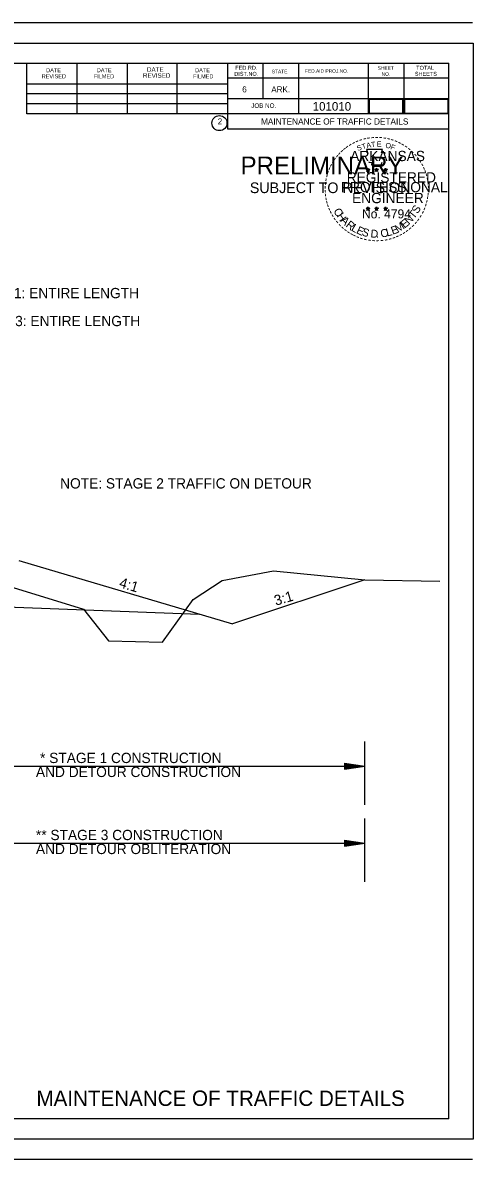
# Model space of a CAD drawing. Extents: x 6125 to 14104, y 8730 to 11067.
# Drawn here: x 9345 to 9784, y 9961 to 11067 of the extents above; entities that cross this region are included whole.
import ezdxf

# ---------------------------------------------------------------- set-up
doc = ezdxf.new("R2010")
doc.units = 0
for name, color, linetype in [('C-PSVP', 7, 'Continuous'), ('GREEN_TXT', 7, 'Continuous'), ('R_Border Notes', 7, 'Continuous'), ('R_No Plot', 7, 'Continuous'), ('R_Proposed Road', 7, 'Continuous'), ('SEAL-INFO', 7, 'Continuous'), ('SIGNATURE', 7, 'Continuous'), ('Stage 1 Construction', 7, 'Continuous'), ('Stage 3', 7, 'Continuous')]:
    doc.layers.add(name, color=color, linetype=linetype)

msp = doc.modelspace()

# ---------------------------------------------------------------- linework, layer by layer
for p, q in [((9340.6, 10543.3), (9548.9, 10481.6)), ((9678, 10524.6), (9548.9, 10481.6)), ((9198.9, 10503.1), (9516.5, 10491.2))]:
    msp.add_line(p, q)
at = {"layer": 'C-PSVP'}
for p, q in [((9679.2, 10924), (9680.9, 10923.5)), ((9679.2, 10924), (9680.4, 10923.8)), ((9679.2, 10924), (9680.3, 10923.4)), ((9679.8, 10922), (9680.9, 10923.5)), ((9679.8, 10922), (9680.4, 10923.2)), ((9679.8, 10922), (9680.9, 10923.1)), ((9680.9, 10925.3), (9680.7, 10924.1)), ((9680.9, 10923.5), (9680.9, 10925.3)), ((9680.9, 10925.3), (9681.1, 10924.1)), ((9682.6, 10924), (9680.9, 10923.5)), ((9682, 10922), (9680.9, 10923.5)), ((9682, 10922), (9680.9, 10923.1)), ((9682.6, 10924), (9681.2, 10923.8)), ((9682, 10922), (9681.3, 10923.5)), ((9682.6, 10924), (9681.6, 10923.5)), ((9687.5, 10924), (9689.2, 10923.5)), ((9687.5, 10924), (9688.8, 10923.8)), ((9687.5, 10924), (9688.7, 10923.4)), ((9688.2, 10922), (9689.2, 10923.5)), ((9688.2, 10922), (9688.8, 10923.2)), ((9688.2, 10922), (9689.2, 10923.1)), ((9689.2, 10925.3), (9689, 10924.1)), ((9689.2, 10923.5), (9689.2, 10925.3)), ((9689.2, 10925.3), (9689.5, 10924.1)), ((9691, 10924), (9689.2, 10923.5)), ((9690.3, 10922), (9689.2, 10923.5)), ((9690.3, 10922), (9689.2, 10923.1)), ((9691, 10924), (9689.6, 10923.8)), ((9690.3, 10922), (9689.6, 10923.5)), ((9691, 10924), (9690, 10923.5)), ((9696.3, 10924), (9698.1, 10923.4)), ((9696.3, 10924), (9697.6, 10923.8)), ((9696.3, 10924), (9697.5, 10923.4)), ((9697, 10921.9), (9698.1, 10923.4)), ((9697, 10921.9), (9697.6, 10923.2)), ((9697, 10921.9), (9698.1, 10923)), ((9698.1, 10925.3), (9697.9, 10924)), ((9698.1, 10923.4), (9698.1, 10925.3)), ((9698.1, 10925.3), (9698.3, 10924)), ((9699.8, 10924), (9698.1, 10923.4)), ((9699.1, 10921.9), (9698.1, 10923.4)), ((9699.1, 10921.9), (9698.1, 10923)), ((9699.8, 10924), (9698.4, 10923.7)), ((9699.1, 10921.9), (9698.4, 10923.4)), ((9699.8, 10924), (9698.8, 10923.5)), ((9679.1, 10886.2), (9680.9, 10885.6)), ((9679.1, 10886.2), (9680.4, 10886)), ((9679.1, 10886.2), (9680.3, 10885.6)), ((9679.8, 10884.1), (9680.9, 10885.6)), ((9679.8, 10884.1), (9680.4, 10885.4)), ((9679.8, 10884.1), (9680.9, 10885.2)), ((9680.9, 10887.4), (9680.7, 10886.2)), ((9680.9, 10885.6), (9680.9, 10887.4)), ((9680.9, 10887.4), (9681.1, 10886.2)), ((9682.6, 10886.2), (9680.9, 10885.6)), ((9681.9, 10884.1), (9680.9, 10885.6)), ((9681.9, 10884.1), (9680.9, 10885.2)), ((9682.6, 10886.2), (9681.2, 10885.9)), ((9681.9, 10884.1), (9681.3, 10885.6)), ((9682.6, 10886.2), (9681.6, 10885.7)), ((9687.5, 10886.2), (9689.2, 10885.6)), ((9687.5, 10886.2), (9688.7, 10886)), ((9687.5, 10886.2), (9688.7, 10885.6)), ((9688.1, 10884.1), (9689.2, 10885.6)), ((9688.1, 10884.1), (9688.8, 10885.4)), ((9688.1, 10884.1), (9689.2, 10885.2)), ((9689.2, 10887.4), (9689, 10886.2)), ((9689.2, 10885.6), (9689.2, 10887.4)), ((9689.2, 10887.4), (9689.5, 10886.2)), ((9691, 10886.2), (9689.2, 10885.6)), ((9690.3, 10884.1), (9689.2, 10885.6)), ((9690.3, 10884.1), (9689.2, 10885.2)), ((9691, 10886.2), (9689.5, 10885.9)), ((9690.3, 10884.1), (9689.6, 10885.6)), ((9691, 10886.2), (9689.9, 10885.7)), ((9696.3, 10886.1), (9698.1, 10885.6)), ((9696.3, 10886.1), (9697.6, 10885.9)), ((9696.3, 10886.1), (9697.5, 10885.5)), ((9697, 10884.1), (9698.1, 10885.6)), ((9697, 10884.1), (9697.6, 10885.3)), ((9697, 10884.1), (9698, 10885.2)), ((9698.1, 10887.4), (9697.9, 10886.1)), ((9699.1, 10884.1), (9698, 10885.2)), ((9698.1, 10885.6), (9698.1, 10887.4)), ((9698.1, 10887.4), (9698.3, 10886.1)), ((9699.8, 10886.1), (9698.1, 10885.6)), ((9699.1, 10884.1), (9698.1, 10885.6)), ((9699.8, 10886.1), (9698.4, 10885.9)), ((9699.1, 10884.1), (9698.4, 10885.5)), ((9699.8, 10886.1), (9698.8, 10885.6))]:
    msp.add_line(p, q, dxfattribs=at)
for points in [[(9679.4, 10943.4), (9680.7, 10939.3)], [(9696.9, 10938.8), (9697.6, 10940.2), (9694.2, 10940.1), (9694.9, 10943.4), (9679.4, 10943.4)], [(9681.8, 10931.3), (9681.8, 10930.9), (9684.6, 10930.8), (9684.4, 10928.4), (9693.7, 10928.4), (9694.7, 10931.1)], [(9680.9, 10925.3), (9682, 10922), (9679.2, 10924), (9682.6, 10924), (9679.8, 10922), (9680.9, 10925.3)], [(9689.2, 10925.3), (9690.3, 10922), (9687.5, 10924), (9691, 10924), (9688.2, 10922), (9689.2, 10925.3)], [(9698.1, 10925.3), (9699.1, 10921.9), (9696.3, 10924), (9699.8, 10924), (9697, 10921.9), (9698.1, 10925.3)], [(9680.9, 10887.4), (9681.9, 10884.1), (9679.1, 10886.2), (9682.6, 10886.2), (9679.8, 10884.1), (9680.9, 10887.4)], [(9689.2, 10887.4), (9690.3, 10884.1), (9687.5, 10886.2), (9691, 10886.2), (9688.1, 10884.1), (9689.2, 10887.4)], [(9698.1, 10887.4), (9699.1, 10884.1), (9696.3, 10886.1), (9699.8, 10886.1), (9697, 10884.1), (9698.1, 10887.4)]]:
    msp.add_lwpolyline(points, dxfattribs=at)
for centre, radius in [((9680.9, 10923.5), 0.861), ((9680.9, 10923.5), 0.723), ((9680.9, 10923.5), 0.579), ((9680.9, 10923.5), 0.495), ((9680.9, 10923.5), 0.374), ((9680.9, 10923.5), 0.248), ((9680.9, 10923.5), 0.148), ((9689.2, 10923.5), 0.861), ((9689.2, 10923.5), 0.723), ((9689.2, 10923.5), 0.579), ((9689.2, 10923.5), 0.495), ((9689.2, 10923.5), 0.374), ((9689.2, 10923.5), 0.248), ((9689.2, 10923.5), 0.148), ((9698.1, 10923.4), 0.861), ((9698.1, 10923.4), 0.723), ((9698.1, 10923.4), 0.579), ((9698.1, 10923.4), 0.495), ((9698.1, 10923.4), 0.374), ((9698.1, 10923.4), 0.248), ((9698.1, 10923.4), 0.148), ((9680.9, 10885.6), 0.861), ((9680.9, 10885.6), 0.723), ((9680.9, 10885.6), 0.579), ((9680.9, 10885.6), 0.495), ((9680.9, 10885.6), 0.374), ((9680.9, 10885.6), 0.248), ((9680.9, 10885.6), 0.148), ((9689.2, 10885.6), 0.861), ((9689.2, 10885.6), 0.723), ((9689.2, 10885.6), 0.579), ((9689.2, 10885.6), 0.495), ((9689.2, 10885.6), 0.374), ((9689.2, 10885.6), 0.248), ((9689.2, 10885.6), 0.148), ((9698.1, 10885.6), 0.861), ((9698.1, 10885.6), 0.723), ((9698.1, 10885.6), 0.579), ((9698.1, 10885.6), 0.495), ((9698.1, 10885.6), 0.374), ((9698.1, 10885.6), 0.248), ((9698.1, 10885.6), 0.148)]:
    msp.add_circle(centre, radius, dxfattribs=at)
at = {"layer": 'GREEN_TXT'}
for p, q in [((9782.7, 11066.7), (8022.7, 11066.7)), ((8178.8, 11027.3), (9759.7, 11027.3)), ((9348.4, 10977.9), (9348.4, 11027.3)), ((9397.7, 10977.9), (9397.7, 11026.3)), ((9446.5, 10977.9), (9446.5, 11026.3)), ((9494.9, 10977.9), (9494.9, 11026.3)), ((9544.2, 11027.3), (9544.2, 10963.3)), ((9578.4, 11027.3), (9578.4, 10992.6)), ((9613.1, 11027.3), (9613.1, 10977.9)), ((9681, 11027.3), (9681, 10977.9)), ((9715.7, 11027.3), (9715.7, 10977.9)), ((9759.7, 10000), (9759.7, 11027.3)), ((9348.4, 11007.2), (9544.2, 11007.2)), ((9759.7, 11012.6), (9544.2, 11012.6)), ((9759.7, 11012.7), (9759.7, 11012.7)), ((9348.4, 10997.9), (9544.2, 10997.9)), ((9348.4, 10988.2), (9544.2, 10988.2)), ((9759.7, 10992.6), (9544.2, 10992.6)), ((9759.7, 10977.9), (9348.4, 10977.9)), ((9544.2, 10963.3), (9759.7, 10963.3)), ((9759.7, 10000), (8178.8, 10000)), ((8022.7, 9960.6), (9782.7, 9960.6))]:
    msp.add_line(p, q, dxfattribs=at)
msp.add_circle((9536.2, 10969), 7.33, dxfattribs=at)
at = {"layer": 'R_No Plot'}
msp.add_lwpolyline([(8214.9, 10518), (8254.7, 10519.4), (8315.6, 10519), (8407.7, 10512.2), (8460.4, 10505.1), (8509.6, 10474.3), (8577.8, 10476.5), (8706.5, 10525.2), (8791.8, 10534.6), (9005.6, 10537.5), (9218.9, 10534.6), (9305.3, 10526.2), (9403.9, 10495.9), (9428.2, 10465.3), (9480.8, 10463.7), (9510.7, 10505.5), (9538.9, 10523.9), (9588.8, 10533.2), (9678, 10524.6), (9750.8, 10523.3)], dxfattribs=at)
at = {"layer": 'R_Proposed Road'}
msp.add_lwpolyline([(9682.1, 10978.6), (9714.7, 10978.6), (9714.7, 10991.9), (9682.1, 10991.9)], close=True, dxfattribs=at)
at = {"layer": 'SEAL-INFO'}
msp.add_lwpolyline([(8116.8, 11046.8), (9783.5, 11046.8), (9783.5, 9980.1), (8116.8, 9980.1)], close=True, dxfattribs=at)
at = {"layer": 'Stage 1 Construction'}
for p, q in [((9678, 10305.7), (9678, 10367.2)), ((9218.9, 10343.2), (9678, 10343.2)), ((9658, 10346.2), (9678, 10343.2)), ((9658, 10346.2), (9658, 10340.2)), ((9658, 10345.7), (9674.7, 10343.2)), ((9658, 10345.1), (9671.2, 10343.2)), ((9658, 10344.6), (9667.9, 10343.2)), ((9658, 10344.1), (9664.5, 10343.2)), ((9658, 10343.6), (9661.2, 10343.2)), ((9658, 10340.2), (9678, 10343.2)), ((9658, 10342.2), (9664.5, 10343.2)), ((9658, 10341.2), (9671.2, 10343.2)), ((9658, 10340.7), (9674.7, 10343.2)), ((9658, 10341.7), (9667.9, 10343.2)), ((9658, 10342.7), (9661.2, 10343.2)), ((9678, 10230.7), (9678, 10292.2)), ((9218.9, 10268.2), (9678, 10268.2)), ((9658, 10271.2), (9678, 10268.2)), ((9658, 10271.2), (9658, 10265.2)), ((9658, 10270.7), (9674.7, 10268.2)), ((9658, 10270.2), (9671.2, 10268.2)), ((9658, 10269.7), (9667.9, 10268.2)), ((9658, 10269.2), (9664.5, 10268.2)), ((9658, 10268.7), (9661.2, 10268.2)), ((9658, 10265.2), (9678, 10268.2)), ((9658, 10267.2), (9664.5, 10268.2)), ((9658, 10266.2), (9671.2, 10268.2)), ((9658, 10265.7), (9674.7, 10268.2)), ((9658, 10266.7), (9667.9, 10268.2)), ((9658, 10267.7), (9661.2, 10268.2))]:
    msp.add_line(p, q, dxfattribs=at)
at = {"layer": 'Stage 3'}
msp.add_lwpolyline([(9716.6, 10978.6), (9758.9, 10978.6), (9758.9, 10991.9), (9716.6, 10991.9)], close=True, dxfattribs=at)

# ---------------------------------------------------------------- texts
at = {"layer": 'C-PSVP'}
for s, height, rotation, p in [('-', 8, 28.7918, (9666.8, 10946.1)), ('-', 8, 24.3072, (9669.9, 10947.7)), ('-', 8, 19.1761, (9673.1, 10949.1)), ('-', 8, 13.6302, (9676.8, 10950.3)), ('-', 8, 10.2193, (9680.2, 10951.1)), ('T', 5, 6.0228, (9684.1, 10945.6)), ('-', 8, 5.8968, (9683.9, 10951.6)), ('-', 8, 0.1862, (9687.7, 10952)), ('E', 5, 0.8323, (9689.6, 10946.1)), ('-', 8, 357.743, (9691.4, 10951.9)), ('-', 8, 352.1617, (9695.1, 10951.6)), ('-', 8, 347.2049, (9698.7, 10951.1)), ('-', 8, 342.3362, (9701.8, 10950.3)), ('-', 8, 337.8551, (9705.5, 10949.2)), ('-', 8, 334.1211, (9708.7, 10947.8)), ('-', 8, 48.4231, (9654.1, 10935.9)), ('-', 8, 42.9622, (9656.3, 10938.3)), ('-', 8, 38.9507, (9658.5, 10940.4)), ('-', 8, 36.2317, (9660.9, 10942.3)), ('-', 8, 34.0636, (9663.8, 10944.3)), ('S', 5, 21.594, (9671.1, 10941.8)), ('T', 5, 16.4036, (9675.7, 10943.5)), ('A', 5, 11.2132, (9679.8, 10944.7)), ('O', 5, 350.4515, (9697.6, 10945.1)), ('F', 5, 340.0707, (9702.4, 10943.9)), ('-', 8, 329.6409, (9711.6, 10946.4)), ('-', 8, 325.8627, (9714.8, 10944.6)), ('-', 8, 320.5297, (9717.8, 10942.5)), ('-', 8, 315.5786, (9720.8, 10940)), ('-', 8, 62.8713, (9646.8, 10925)), ('-', 8, 58.0706, (9648.4, 10928)), ('-', 8, 54.2325, (9650, 10930.7)), ('-', 8, 50.6142, (9652.1, 10933.5)), ('-', 8, 309.8797, (9723.7, 10937.3)), ('-', 8, 306.6522, (9726.3, 10934.3)), ('-', 7, 303.6753, (9728.7, 10931.4)), ('-', 8, 299.6684, (9730.3, 10928.4)), ('-', 8, 75.461, (9643.5, 10915.2)), ('-', 8, 72.3945, (9644.4, 10918.8)), ('-', 8, 67.7743, (9645.5, 10921.9)), ('-', 8, 294.6628, (9731.9, 10925.3)), ('-', 8, 290.5728, (9733.2, 10922.5)), ('-', 8, 285.1233, (9734.4, 10919.6)), ('-', 8, 89.0622, (9642.3, 10904.7)), ('-', 8, 85.1863, (9642.4, 10908.2)), ('-', 8, 81.2013, (9642.8, 10911.6)), ('-', 8, 280.5493, (9735.4, 10915.9)), ('-', 8, 276.5962, (9736.2, 10912)), ('-', 8, 274.3301, (9736.5, 10908.4)), ('-', 8, 94.1959, (9642.5, 10901.1)), ('-', 8, 98.9479, (9642.8, 10897.7)), ('-', 8, 101.7149, (9643.5, 10894.1)), ('-', 8, 260.9953, (9736.2, 10898.6)), ('-', 8, 263.5172, (9736.6, 10901.9)), ('-', 8, 269.9407, (9736.7, 10905.2)), ('-', 8, 105.4578, (9644.3, 10891.1)), ('-', 8, 109.0874, (9645.4, 10887.9)), ('-', 8, 114.0643, (9646.7, 10884.9)), ('C', 7.7, 296.9133, (9647, 10883.9)), ('T', 7.7, 51.5114, (9725.7, 10875.1)), ('S', 7.7, 57.878, (9729.3, 10880.3)), ('-', 8, 247.8887, (9733.7, 10888.3)), ('-', 8, 255.7626, (9734.7, 10891.8)), ('-', 8, 255.7626, (9735.7, 10895.3)), ('-', 8, 115.7289, (9648.2, 10881.9)), ('-', 8, 120.4471, (9650, 10878.9)), ('-', 8, 125.8934, (9652, 10876.1)), ('-', 8, 130.7181, (9654.3, 10873.4)), ('H', 7.7, 303.2799, (9650, 10878.7)), ('A', 7.7, 316.013, (9653.6, 10873.6)), ('R', 7.7, 322.3796, (9658.7, 10868.7)), ('E', 7.7, 38.7783, (9716.4, 10866.2)), ('N', 7.7, 45.1449, (9720.9, 10869.9)), ('-', 8, 231.2538, (9726.2, 10875.3)), ('-', 8, 233.8452, (9728.4, 10878.1)), ('-', 8, 239.0712, (9730.4, 10881.4)), ('-', 8, 244.6197, (9732.4, 10885.1)), ('-', 8, 134.2238, (9656.9, 10870.6)), ('-', 8, 138.9338, (9659.5, 10868.3)), ('-', 8, 144.6463, (9662.3, 10866.3)), ('-', 8, 148.0898, (9665.1, 10864.4)), ('-', 8, 151.5704, (9668, 10862.8)), ('L', 7.7, 328.7461, (9663.9, 10864.9)), ('E', 7.7, 335.1127, (9668.9, 10862.1)), ('S', 7.7, 341.4792, (9674.2, 10860)), ('D', 7.7, 354.2124, (9683.1, 10857.9)), ('C', 7.7, 6.9455, (9693.5, 10857.7)), ('L', 7.7, 13.3121, (9699.4, 10858.7)), ('E', 7.7, 19.6786, (9704.9, 10860.3)), ('M', 7.7, 32.4117, (9710, 10862.1)), ('-', 8, 212.2491, (9715.8, 10865.6)), ('-', 8, 215.7363, (9718.5, 10867.6)), ('-', 8, 221.0851, (9721.2, 10869.9)), ('-', 8, 225.7653, (9723.8, 10872.5)), ('-', 8, 154.6002, (9670.6, 10861.6)), ('-', 8, 158.5612, (9673.7, 10860.3)), ('-', 8, 162.7983, (9677.1, 10859.2)), ('-', 8, 167.5555, (9680.7, 10858.4)), ('-', 8, 173.1155, (9684.6, 10857.9)), ('-', 8, 176.5183, (9688.3, 10857.6)), ('-', 8, 181.5918, (9692, 10857.7)), ('.', 7.7, 0.5789, (9688.9, 10857.5)), ('-', 8, 185.8167, (9696.1, 10858.1)), ('-', 8, 191.2858, (9699.8, 10858.7)), ('-', 8, 195.4743, (9703.4, 10859.7)), ('-', 8, 200.7184, (9706.8, 10860.9)), ('-', 8, 204.2516, (9709.9, 10862.3)), ('-', 8, 207.3568, (9713, 10863.9))]:
    msp.add_text(s, height=height, rotation=rotation, dxfattribs=at).set_placement(p)
for s, height, p in [('ARKANSAS', 10, (9663.6, 10932)), ('REGISTERED', 10, (9660.2, 10911.2)), ('PROFESSIONAL', 10, (9654.5, 10901.7)), ('ENGINEER', 10, (9665.4, 10891.1)), ('No. 4794', 8.78, (9675.1, 10876.3))]:
    msp.add_text(s, height=height, dxfattribs=at).set_placement(p)
at = {"layer": 'GREEN_TXT'}
for s, height, p in [('DATE', 3.91, (9367.4, 11018.5)), ('DATE', 3.91, (9416.7, 11018.5)), ('REVISED', 4.4, (9461.7, 11013.1)), ('DATE', 4.4, (9465.6, 11019)), ('DATE', 3.91, (9512.5, 11018.5)), ('DIST.NO.', 3.91, (9550.6, 11015)), ('FED.RD.', 3.91, (9551.6, 11020.9)), ('STATE', 3.42, (9587.2, 11017.5)), ('FED.AID PROJ.NO.', 3.42, (9619.5, 11018)), ('SHEET', 3.42, (9690.3, 11020.9)), ('NO.', 3.42, (9694.2, 11015)), ('SHEETS', 3.91, (9726.5, 11015)), ('TOTAL', 3.91, (9727.9, 11020.9)), ('REVISED', 3.91, (9363, 11012.6)), ('FILMED', 3.91, (9413.8, 11012.6)), ('FILMED', 3.91, (9510.5, 11012.6)), ('6', 5.86, (9558.4, 10998.9)), ('ARK.', 5.86, (9586.7, 10998.9)), ('JOB NO.', 4.4, (9567.2, 10983.8)), ('2', 5.86, (9534.5, 10967.7)), ('MAINTENANCE OF TRAFFIC DETAILS', 15, (9357.9, 10012.5))]:
    msp.add_text(s, height=height, dxfattribs=at).set_placement(p)
at = {"layer": 'R_Border Notes'}
for s, height, p in [('101010', 8.4, (9627, 10981.1)), ('MAINTENANCE OF TRAFFIC DETAILS', 6, (9576.7, 10967.6))]:
    msp.add_text(s, height=height, dxfattribs=at).set_placement(p)
at = {"layer": 'SIGNATURE'}
for s, height, p in [('PRELIMINARY', 17.5, (9556.8, 10919)), ('SUBJECT TO REVISION', 10.376, (9565.8, 10900.9))]:
    msp.add_text(s, height=height, dxfattribs=at).set_placement(p)
at = {"layer": 'Stage 1 Construction'}
for s, p in [('* STAGE 1: ENTIRE LENGTH', (9278, 10798.6)), ('** STAGE 3: ENTIRE LENGTH', (9274, 10771.4)), ('NOTE: STAGE 2 TRAFFIC ON DETOUR', (9381, 10613.4)), ('* STAGE 1 CONSTRUCTION', (9361.4, 10346.2)), ('AND DETOUR CONSTRUCTION', (9357.4, 10332.6)), ('** STAGE 3 CONSTRUCTION', (9357.4, 10271.2)), ('AND DETOUR OBLITERATION', (9357.4, 10257.6))]:
    msp.add_text(s, height=10, dxfattribs=at).set_placement(p)
for s, rotation, p in [('4:1', 343.4219, (9437.8, 10517.5)), ('3:1', 16.0306, (9591.1, 10499.3))]:
    msp.add_text(s, height=10, rotation=rotation, dxfattribs=at).set_placement(p)

doc.saveas('drawing.dxf')
